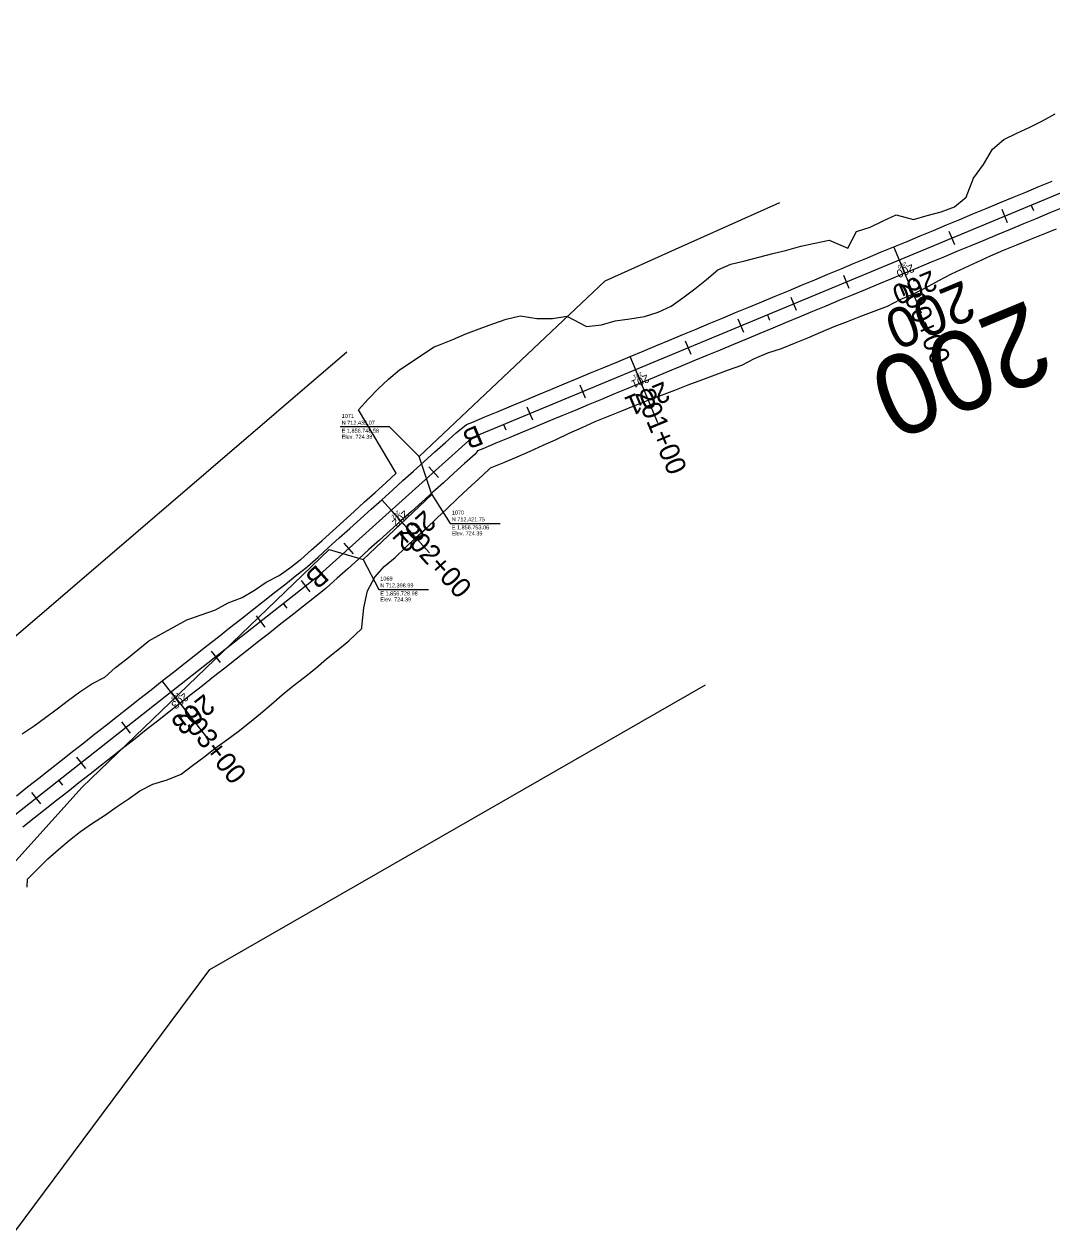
# Model space of a CAD drawing. Extents: x 1823824 to 1861612, y 706975 to 726130.
# Drawn here: x 1825141.5 to 1825501.4, y 712201 to 712623.2 of the extents above; entities that cross this region are included whole.
import ezdxf

# ---------------------------------------------------------------- set-up
doc = ezdxf.new("R2010")
doc.units = 0
for name, color, linetype in [('DR_X_Flood_Boundary', 7, 'Continuous'), ('GE_X_CL_10', 7, 'Continuous'), ('GE_X_CL_100', 7, 'Continuous'), ('GE_X_CL_20', 7, 'Continuous'), ('GE_X_CL_200', 7, 'Continuous'), ('GE_X_CL_50', 7, 'Continuous'), ('RW_X_Esmt_FL', 7, 'Continuous'), ('SC_Scratch1', 7, 'Continuous'), ('SC_Scratch2', 7, 'Continuous'), ('SC_Scratch5', 7, 'Continuous'), ('SC_Scratch6', 7, 'Continuous')]:
    doc.layers.add(name, color=color, linetype=linetype)

msp = doc.modelspace()

# ---------------------------------------------------------------- linework, layer by layer
at = {"layer": 'DR_X_Flood_Boundary'}
for p, q in [((1825646.54, 712623.21), (1825298.33, 712478.48)), ((1825298.33, 712478.48), (1825243.83, 712429.46)), ((1825243.83, 712429.46), (1825086.51, 712305.67))]:
    msp.add_line(p, q, dxfattribs=at)
at = {"layer": 'GE_X_CL_10'}
for p, q in [((1825494.11, 712559.86), (1825494.5, 712558.94)), ((1825447.94, 712540.67), (1825448.33, 712539.74)), ((1825401.77, 712521.48), (1825402.16, 712520.55)), ((1825355.6, 712502.29), (1825355.99, 712501.36)), ((1825309.43, 712483.1), (1825309.82, 712482.17)), ((1825270.09, 712453.09), (1825270.76, 712452.34)), ((1825232.3, 712420.39), (1825232.91, 712419.6)), ((1825193, 712389.47), (1825193.62, 712388.68)), ((1825153.71, 712358.55), (1825154.33, 712357.76))]:
    msp.add_line(p, q, dxfattribs=at)
at = {"layer": 'GE_X_CL_100'}
for p, q in [((1825447.94, 712540.67), (1825451.78, 712531.43)), ((1825355.6, 712502.29), (1825359.44, 712493.05)), ((1825270.09, 712453.09), (1825276.78, 712445.65)), ((1825193, 712389.47), (1825199.19, 712381.61))]:
    msp.add_line(p, q, dxfattribs=at)
at = {"layer": 'GE_X_CL_20'}
for p, q in [((1825494.11, 712559.86), (1825494.88, 712558.01)), ((1825447.94, 712540.67), (1825448.71, 712538.82)), ((1825401.77, 712521.48), (1825402.54, 712519.63)), ((1825355.6, 712502.29), (1825356.37, 712500.44)), ((1825309.43, 712483.1), (1825310.2, 712481.25)), ((1825270.09, 712453.09), (1825271.43, 712451.6)), ((1825232.3, 712420.39), (1825233.53, 712418.82)), ((1825193, 712389.47), (1825194.24, 712387.9)), ((1825153.71, 712358.55), (1825154.95, 712356.98))]:
    msp.add_line(p, q, dxfattribs=at)
at = {"layer": 'GE_X_CL_200'}
for p, q in [((1825447.94, 712540.67), (1825455.62, 712522.2)), ((1825355.6, 712502.29), (1825363.28, 712483.82)), ((1825270.09, 712453.09), (1825283.47, 712438.21)), ((1825193, 712389.47), (1825205.37, 712373.75))]:
    msp.add_line(p, q, dxfattribs=at)
at = {"layer": 'GE_X_CL_50'}
for p, q in [((1825447.94, 712540.67), (1825449.86, 712536.05)), ((1825355.6, 712502.29), (1825357.52, 712497.67)), ((1825270.09, 712453.09), (1825273.44, 712449.37)), ((1825193, 712389.47), (1825196.09, 712385.54))]:
    msp.add_line(p, q, dxfattribs=at)
at = {"layer": 'RW_X_Esmt_FL'}
for p, q in [((1825058.79, 712340.8), (1825254.52, 712508.57)), ((1825206.62, 712292.45), (1825380.04, 712392.08)), ((1825138.53, 712200.98), (1825206.62, 712292.45))]:
    msp.add_line(p, q, dxfattribs=at)
at = {"layer": 'SC_Scratch1'}
for points in [[(1825098.5, 712286.03), (1825161.91, 712356.25), (1825248.35, 712439.43), (1825260.24, 712435.86), (1825284.32, 712458.62), (1825279.84, 712471.94), (1825344.91, 712533.42), (1825353.06, 712536.99), (1825369.63, 712544.42), (1825397.29, 712556.8), (1825406.13, 712560.83)], [(1825098.5, 712286.03), (1825161.91, 712356.25), (1825248.35, 712439.43), (1825260.24, 712435.86), (1825284.32, 712458.62), (1825279.84, 712471.94), (1825344.91, 712533.42), (1825353.06, 712536.99), (1825369.63, 712544.42), (1825397.29, 712556.8), (1825406.13, 712560.83)], [(1825279.84, 712471.94), (1825269.46, 712482.34), (1825252.18, 712482.34)], [(1825284.32, 712458.62), (1825290.72, 712448.53), (1825308.26, 712448.53)], [(1825260.24, 712435.86), (1825265.7, 712425.42), (1825283.1, 712425.42)]]:
    msp.add_lwpolyline(points, dxfattribs=at)
at = {"layer": 'SC_Scratch2'}
for points in [[(1825140.86, 712374.87), (1825145.03, 712377.66), (1825149.05, 712380.63), (1825153.07, 712383.62), (1825157.07, 712386.62), (1825161.05, 712389.64), (1825165.29, 712392.34), (1825169.78, 712394.72), (1825173.48, 712398.1), (1825177.47, 712401.12), (1825181.39, 712404.23), (1825185.22, 712407.44), (1825189.67, 712409.87), (1825194.08, 712412.35), (1825198.49, 712414.83), (1825203.54, 712416.5), (1825208.55, 712418.23), (1825212.98, 712420.67), (1825217.85, 712422.57), (1825222.18, 712425.15), (1825226.31, 712428), (1825230.85, 712430.31), (1825234.91, 712433.23), (1825238.2, 712435.72), (1825238.44, 712435.93), (1825242.18, 712439.26), (1825245.9, 712442.59), (1825249.62, 712445.94), (1825253.35, 712449.27), (1825257.05, 712452.63), (1825260.74, 712456.01), (1825264.44, 712459.37), (1825268.15, 712462.73), (1825271.82, 712466.12), (1825258.63, 712488.26), (1825261.98, 712492.02), (1825265.44, 712495.65), (1825269.14, 712499.01), (1825272.99, 712502.2), (1825285.11, 712510.29), (1825287, 712511), (1825291.63, 712512.9), (1825296.22, 712514.89), (1825300.9, 712516.65), (1825305.6, 712518.36), (1825310.35, 712519.97), (1825315.26, 712521.17), (1825321.08, 712520.2), (1825326.49, 712520.21), (1825331.58, 712521), (1825338.46, 712517.46), (1825343.65, 712518.02), (1825348.5, 712519.37), (1825353.63, 712520.05), (1825358.69, 712520.92), (1825363.49, 712522.39), (1825368.03, 712524.5), (1825372.21, 712527.47), (1825376.32, 712530.6), (1825380.4, 712533.82), (1825384.4, 712537.21), (1825389, 712539.17), (1825393.9, 712540.42), (1825398.8, 712541.67), (1825403.69, 712542.92), (1825408.59, 712544.16), (1825413.42, 712545.55), (1825418.41, 712546.59), (1825423.37, 712547.68), (1825429.97, 712544.83), (1825432.94, 712550.7), (1825437.73, 712552.2), (1825442.25, 712554.37), (1825446.79, 712556.47), (1825452.86, 712554.88), (1825457.72, 712556.22), (1825462.58, 712557.57), (1825467.26, 712559.32), (1825471.3, 712562.63), (1825473.94, 712569.32), (1825477.38, 712574.05), (1825480.55, 712579.46), (1825484.57, 712582.82), (1825489.06, 712585.04), (1825493.59, 712587.16), (1825498.1, 712589.34), (1825502.47, 712591.87)], [(1825138.83, 712353.2), (1825142.76, 712356.29), (1825146.69, 712359.39), (1825150.62, 712362.48), (1825154.55, 712365.57), (1825158.47, 712368.66), (1825162.4, 712371.75), (1825166.33, 712374.85), (1825170.26, 712377.94), (1825174.19, 712381.03), (1825178.12, 712384.12), (1825182.05, 712387.21), (1825185.98, 712390.31), (1825189.91, 712393.4), (1825193.84, 712396.49), (1825197.77, 712399.58), (1825201.7, 712402.67), (1825205.63, 712405.77), (1825209.56, 712408.86), (1825213.49, 712411.95), (1825217.41, 712415.04), (1825221.34, 712418.13), (1825225.27, 712421.23), (1825229.2, 712424.32), (1825233.13, 712427.41), (1825237.06, 712430.5), (1825240.48, 712433.18), (1825240.73, 712433.4), (1825244.44, 712436.74), (1825248.16, 712440.08), (1825251.88, 712443.43), (1825255.6, 712446.77), (1825259.31, 712450.12), (1825263.03, 712453.46), (1825266.75, 712456.8), (1825270.47, 712460.15), (1825274.18, 712463.49), (1825277.9, 712466.83), (1825281.62, 712470.18), (1825285.34, 712473.52), (1825289.05, 712476.86), (1825292.77, 712480.21), (1825296.41, 712483.1), (1825298.28, 712483.87), (1825302.89, 712485.79), (1825307.51, 712487.71), (1825312.13, 712489.63), (1825316.75, 712491.55), (1825321.36, 712493.47), (1825325.98, 712495.39), (1825330.6, 712497.31), (1825335.21, 712499.23), (1825339.83, 712501.15), (1825344.45, 712503.07), (1825349.07, 712504.98), (1825353.68, 712506.9), (1825358.3, 712508.82), (1825362.92, 712510.74), (1825367.53, 712512.66), (1825372.15, 712514.58), (1825376.77, 712516.5), (1825381.38, 712518.42), (1825386, 712520.34), (1825390.62, 712522.26), (1825395.24, 712524.17), (1825399.85, 712526.09), (1825404.47, 712528.01), (1825409.09, 712529.93), (1825413.7, 712531.85), (1825418.32, 712533.77), (1825422.94, 712535.69), (1825427.56, 712537.61), (1825432.17, 712539.53), (1825436.79, 712541.45), (1825441.41, 712543.37), (1825446.02, 712545.28), (1825450.64, 712547.2), (1825455.26, 712549.12), (1825459.87, 712551.04), (1825464.49, 712552.96), (1825469.11, 712554.88), (1825473.73, 712556.8), (1825478.34, 712558.72), (1825482.96, 712560.64), (1825487.58, 712562.56), (1825492.19, 712564.47), (1825496.81, 712566.39), (1825501.43, 712568.31)], [(1825505.27, 712559.08), (1825500.65, 712557.16), (1825496.03, 712555.24), (1825491.42, 712553.32), (1825486.8, 712551.4), (1825482.18, 712549.48), (1825477.56, 712547.56), (1825472.95, 712545.65), (1825468.33, 712543.73), (1825463.71, 712541.81), (1825459.1, 712539.89), (1825454.48, 712537.97), (1825449.86, 712536.05), (1825445.24, 712534.13), (1825440.63, 712532.21), (1825436.01, 712530.29), (1825431.39, 712528.37), (1825426.78, 712526.46), (1825422.16, 712524.54), (1825417.54, 712522.62), (1825412.92, 712520.7), (1825408.31, 712518.78), (1825403.69, 712516.86), (1825399.07, 712514.94), (1825394.46, 712513.02), (1825389.84, 712511.1), (1825385.22, 712509.18), (1825380.61, 712507.26), (1825375.99, 712505.35), (1825371.37, 712503.43), (1825366.75, 712501.51)], [(1825142.63, 712321.21), (1825142.7, 712324.02), (1825146.27, 712327.57), (1825149.84, 712331.13), (1825153.61, 712334.42), (1825157.4, 712337.68), (1825161.34, 712340.76), (1825165.47, 712343.6), (1825169.67, 712346.35), (1825173.8, 712349.18), (1825177.94, 712352.01), (1825182.03, 712354.9), (1825186.55, 712357.24), (1825191.67, 712358.82), (1825196.48, 712360.79), (1825200.51, 712363.76), (1825204.51, 712366.76), (1825208.45, 712369.84), (1825212.47, 712372.81), (1825216.53, 712375.74), (1825220.43, 712378.87), (1825224.3, 712382.03), (1825228.13, 712385.25), (1825231.93, 712388.52), (1825235.76, 712391.72), (1825239.74, 712394.75), (1825243.62, 712397.91), (1825247.44, 712401.13), (1825251.32, 712404.29), (1825255.25, 712407.39), (1825259.73, 712411.77), (1825259.78, 712412.21), (1825260.44, 712418.95), (1825261.81, 712424.91), (1825264.27, 712429.65), (1825267.62, 712433.41), (1825271.45, 712436.62), (1825275.1, 712440.04), (1825278.65, 712443.57), (1825282.38, 712446.9), (1825286.04, 712450.3), (1825289.63, 712453.79), (1825293.27, 712457.22), (1825296.93, 712460.63), (1825300.6, 712464.03), (1825304.27, 712467.42), (1825304.87, 712468.01), (1825304.87, 712468.01), (1825309.51, 712469.88), (1825314.14, 712471.76), (1825318.69, 712473.84), (1825323.25, 712475.89), (1825327.83, 712477.9), (1825332.35, 712480.05), (1825336.9, 712482.13), (1825341.49, 712484.13), (1825346.12, 712486.02), (1825350.75, 712487.91), (1825355.37, 712489.81), (1825360.01, 712491.69), (1825364.71, 712493.4), (1825369.39, 712495.16), (1825374.06, 712496.95), (1825378.75, 712498.7), (1825383.42, 712500.48), (1825388.13, 712502.2), (1825392.83, 712503.91), (1825397.27, 712506.26), (1825401.89, 712508.16), (1825406.66, 712509.71), (1825411.29, 712511.61), (1825415.93, 712513.48), (1825420.51, 712515.49), (1825425.14, 712517.37), (1825429.8, 712519.18), (1825434.46, 712520.99), (1825439.11, 712522.83), (1825443.82, 712524.54), (1825448.26, 712526.87), (1825452.86, 712528.84), (1825457.33, 712531.11), (1825461.73, 712533.56), (1825466.18, 712535.88), (1825470.72, 712537.97), (1825475.26, 712540.07), (1825479.81, 712542.16), (1825484.42, 712544.11), (1825489.05, 712545.98), (1825493.69, 712547.85), (1825498.33, 712549.72), (1825502.95, 712551.63)], [(1825366.75, 712501.51), (1825362.14, 712499.59), (1825357.52, 712497.67), (1825352.9, 712495.75), (1825348.29, 712493.83), (1825343.67, 712491.91), (1825339.05, 712489.99), (1825334.43, 712488.07), (1825329.82, 712486.16), (1825325.2, 712484.24), (1825320.58, 712482.32), (1825315.97, 712480.4), (1825311.35, 712478.48), (1825306.73, 712476.56), (1825302.12, 712474.64), (1825300.25, 712473.87), (1825299.46, 712472.77), (1825295.74, 712469.43), (1825292.02, 712466.08), (1825288.31, 712462.74), (1825284.59, 712459.4), (1825280.87, 712456.05), (1825277.15, 712452.71), (1825273.44, 712449.37), (1825269.72, 712446.02), (1825266, 712442.68), (1825262.28, 712439.34), (1825258.57, 712435.99), (1825254.85, 712432.65), (1825251.13, 712429.31), (1825247.41, 712425.96), (1825247.17, 712425.74), (1825243.25, 712422.64), (1825239.32, 712419.55), (1825235.39, 712416.46), (1825231.46, 712413.37), (1825227.53, 712410.27), (1825223.6, 712407.18), (1825219.67, 712404.09), (1825215.74, 712401), (1825211.81, 712397.91), (1825207.88, 712394.81), (1825203.95, 712391.72), (1825200.02, 712388.63), (1825196.09, 712385.54), (1825192.16, 712382.45), (1825188.23, 712379.35), (1825184.31, 712376.26), (1825180.38, 712373.17), (1825176.45, 712370.08), (1825172.52, 712366.99), (1825168.59, 712363.89), (1825164.66, 712360.8), (1825160.73, 712357.71), (1825156.8, 712354.62), (1825152.87, 712351.53), (1825148.94, 712348.43), (1825145.01, 712345.34), (1825141.08, 712342.25)]]:
    msp.add_lwpolyline(points, dxfattribs=at)
at = {"layer": 'SC_Scratch5'}
for points in [[(1825485.84, 712553.71), (1825483.92, 712558.33)], [(1825467.37, 712546.04), (1825465.45, 712550.65)], [(1825449.86, 712536.05), (1825446.02, 712545.29)], [(1825430.44, 712530.68), (1825428.52, 712535.3)], [(1825411.97, 712523.01), (1825410.05, 712527.62)], [(1825393.5, 712515.33), (1825391.58, 712519.95)], [(1825375.03, 712507.65), (1825373.11, 712512.27)], [(1825357.52, 712497.67), (1825353.68, 712506.9)], [(1825338.09, 712492.3), (1825336.17, 712496.92)], [(1825319.63, 712484.63), (1825317.71, 712489.24)], [(1825301.16, 712476.95), (1825299.24, 712481.57)], [(1825286.64, 712464.6), (1825283.29, 712468.32)], [(1825273.44, 712449.37), (1825266.75, 712456.8)], [(1825256.89, 712437.85), (1825253.55, 712441.57)], [(1825241.7, 712424.61), (1825238.61, 712428.54)], [(1825225.98, 712412.24), (1825222.89, 712416.17)], [(1825210.27, 712399.87), (1825207.17, 712403.8)], [(1825196.09, 712385.54), (1825189.91, 712393.4)], [(1825178.83, 712375.14), (1825175.74, 712379.07)], [(1825163.11, 712362.77), (1825160.02, 712366.7)], [(1825147.4, 712350.4), (1825144.3, 712354.33)]]:
    msp.add_lwpolyline(points, dxfattribs=at)

# ---------------------------------------------------------------- texts
at = {"layer": 'GE_X_CL_10'}
for s, rotation, p in [('200', 202.5699, (1825450.2, 712539.98)), ('201', 202.5699, (1825357.62, 712501.5)), ('202', 221.9668, (1825272.43, 712453.17)), ('203', 218.1993, (1825195.35, 712389.41))]:
    msp.add_text(s, height=1.4, rotation=rotation, dxfattribs=at).set_placement(p)
at = {"layer": 'GE_X_CL_100'}
msp.add_text('200', height=14, rotation=202.5699, dxfattribs=at).set_placement((1825470.55, 712533.82))
at = {"layer": 'GE_X_CL_20'}
for s, rotation, p in [('200', 202.5699, (1825452.46, 712539.3)), ('201', 202.5699, (1825359.63, 712500.71)), ('202', 221.9668, (1825274.76, 712453.25)), ('203', 218.1993, (1825197.7, 712389.35))]:
    msp.add_text(s, height=2.8, rotation=rotation, dxfattribs=at).set_placement(p)
at = {"layer": 'GE_X_CL_200'}
msp.add_text('200', height=28, rotation=202.5699, dxfattribs=at).set_placement((1825493.15, 712526.97))
at = {"layer": 'GE_X_CL_50'}
for s, rotation, p in [('200', 202.5699, (1825459.25, 712537.24)), ('201', 202.5699, (1825365.68, 712498.35)), ('202', 221.9668, (1825281.77, 712453.5)), ('203', 218.1993, (1825204.74, 712389.16))]:
    msp.add_text(s, height=7, rotation=rotation, dxfattribs=at).set_placement(p)
at = {"layer": 'SC_Scratch1'}
for s, p in [(' 1071', (1825252.18, 712485.44)), (' N 712,435.07', (1825252.18, 712483.04)), (' E 1,856,748.58', (1825252.18, 712480.24)), (' Elev. 724.38 ', (1825252.18, 712478.14)), (' 1070', (1825290.72, 712451.63)), (' N 712,421.75', (1825290.72, 712449.23)), (' E 1,856,753.06', (1825290.72, 712446.43)), (' Elev. 724.39 ', (1825290.72, 712444.33)), (' 1069', (1825265.7, 712428.52)), (' N 712,398.99', (1825265.7, 712426.12)), (' E 1,856,728.98', (1825265.7, 712423.32)), (' Elev. 724.39 ', (1825265.7, 712421.22))]:
    msp.add_text(s, height=1.4, dxfattribs=at).set_placement(p)
at = {"layer": 'SC_Scratch5'}
for s, rotation, p in [('200+00', 292.5699, (1825447.59, 712532.4)), ('201+00', 292.5699, (1825355.25, 712494.02)), ('202+00', 311.9668, (1825272.51, 712445.17)), ('203+00', 308.1993, (1825194.89, 712381.41))]:
    msp.add_text(s, height=7, rotation=rotation, dxfattribs=at).set_placement(p)
at = {"layer": 'SC_Scratch6'}
for rotation, p in [(202.5699, (1825300.22, 712483.06)), (221.9668, (1825244.09, 712434.4))]:
    msp.add_text('B', height=7, rotation=rotation, dxfattribs=at).set_placement(p)

doc.saveas('drawing.dxf')
